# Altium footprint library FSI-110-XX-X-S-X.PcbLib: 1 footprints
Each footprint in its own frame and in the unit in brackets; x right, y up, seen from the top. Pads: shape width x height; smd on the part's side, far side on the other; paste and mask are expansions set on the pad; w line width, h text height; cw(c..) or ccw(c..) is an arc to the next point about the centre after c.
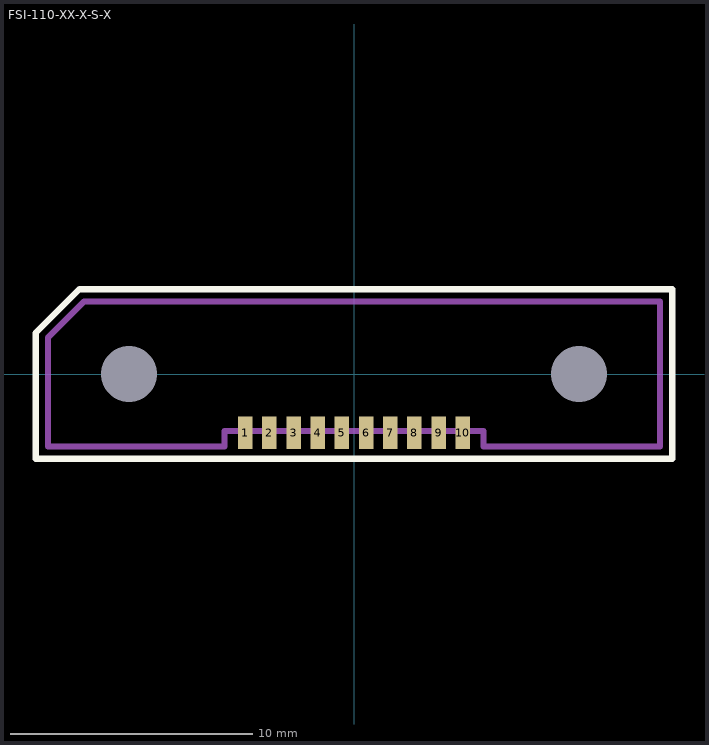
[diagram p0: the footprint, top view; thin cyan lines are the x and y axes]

## FSI-110-XX-X-S-X [mm]
pads (12):
  rect 0.6x1.35 smd mask+0.05: 1(-4.5,-2.425) 2(-3.5,-2.425) 3(-2.5,-2.425) 4(-1.5,-2.425) 5(-0.5,-2.425) 6(0.5,-2.425) 7(1.5,-2.425) 8(2.5,-2.425) 9(3.5,-2.425) 10(4.5,-2.425)
  round 0 hole 2.3 unplated: 11(-9.3,0) 12(9.3,0)
Top Overlay:
  lines w0.254: -13.15,-3.5 -13.15,1.7 -11.35,3.5 13.15,3.5 13.15,-3.5 -13.15,-3.5
Mechanical 1:
  lines w0.254: -12.65,-3 -12.65,1.5 -11.15,3 12.65,3 12.65,-3 5.35,-3 5.35,-2.36 -5.35,-2.36 -5.35,-3 -12.65,-3
  text "J1" at -0.446,-0.457 h0.76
